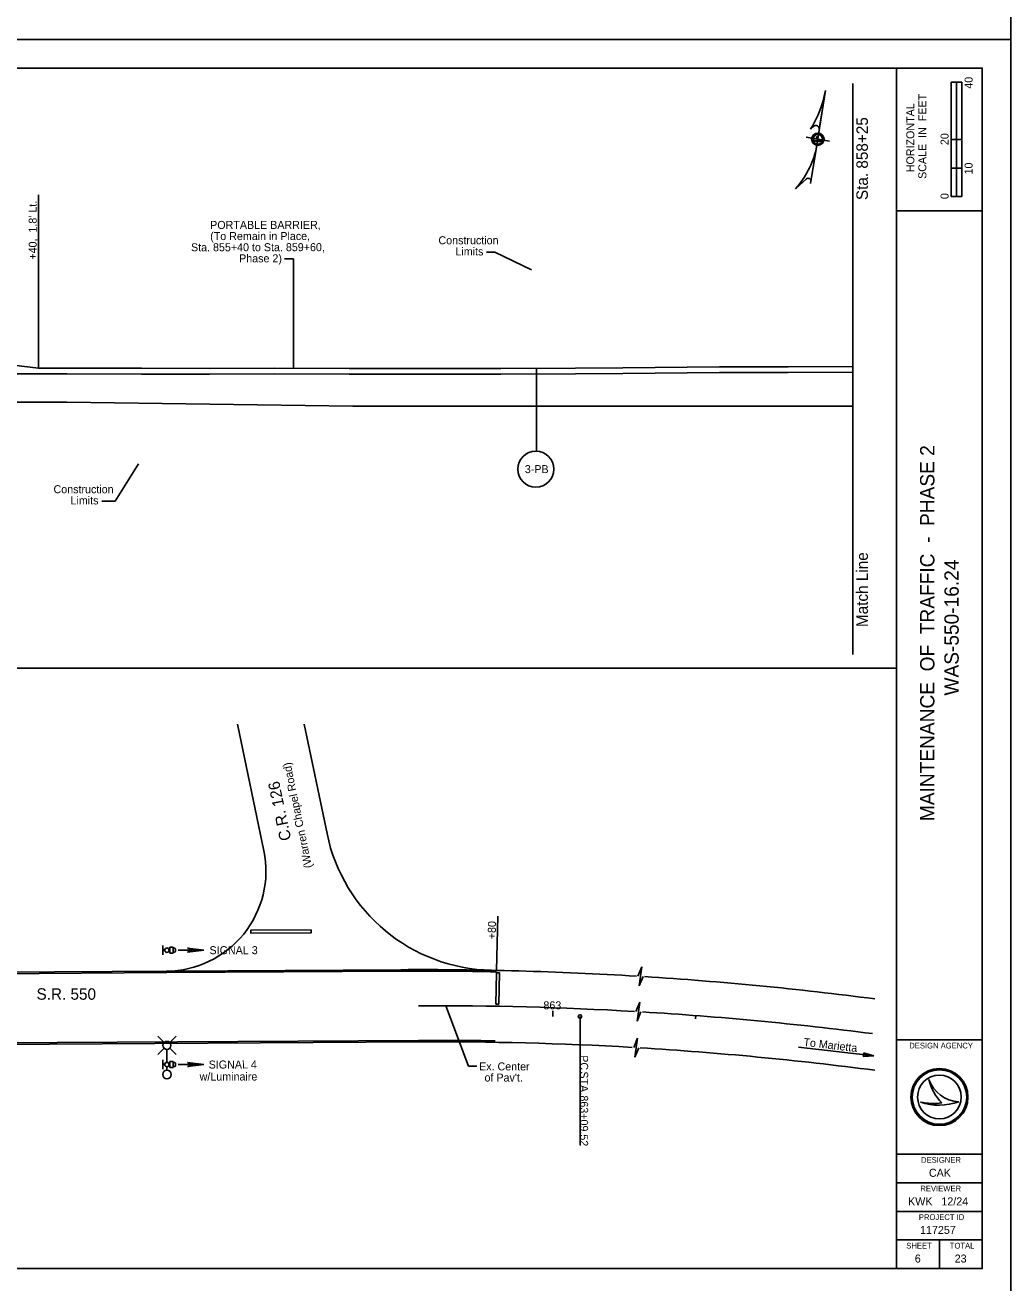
# Model space of a CAD drawing. Extents: x -1395 to 1843, y -1176 to 1887.
# Drawn here: x 335.1 to 680, y -435 to 5 of the extents above; entities that cross this region are included whole.
import ezdxf

# ---------------------------------------------------------------- set-up
doc = ezdxf.new("R2010")
doc.units = 0
for name, color, linetype in [('Default', 7, 'Continuous'), ('DR_P_Headwall', 7, 'Continuous'), ('DR_X_Ditch', 7, 'Continuous'), ('PV_X_COP', 7, 'Continuous'), ('SH_Border', 7, 'Continuous'), ('SH_Cut_Line', 7, 'Continuous'), ('SH_Major_Grid_Line', 7, 'Continuous'), ('SH_Masking', 7, 'Continuous'), ('SH_Named_Boundary', 7, 'Continuous'), ('SH_Text', 7, 'Continuous'), ('XS_P_Annotation', 7, 'Continuous'), ('XS_P_Headwall', 7, 'Continuous'), ('XS_P_Pavt_Surface', 7, 'Continuous')]:
    doc.layers.add(name, color=color, linetype=linetype)

msp = doc.modelspace()

# ---------------------------------------------------------------- linework, layer by layer
at = {"layer": 'Default'}
for p, q in [((628.34, -355.8), (632.08, -355.62)), ((628.34, -355.8), (628.34, -355.8)), ((632.08, -355.62), (628.47, -354.57)), ((628.47, -354.57), (628.47, -354.57))]:
    msp.add_line(p, q, dxfattribs=at)
for centre, radius, start, end in [((479.68, -1525.67), 1187.6, 86.68927, 90.33829), ((479.68, -1525.67), 1187.6, 82.65249, 86.55287), ((627.47, -355.08), 1.12, 320.4114, 27.0922)]:
    msp.add_arc(centre, radius, start, end, dxfattribs=at)
at = {"layer": 'DR_P_Headwall'}
for points in [[(435.21, -311.5), (435.21, -312.5), (414.02, -312.63), (414.01, -311.63)], [(500.8, -337.51), (499.8, -337.49), (500.03, -326.49), (501.03, -326.51)]]:
    msp.add_lwpolyline(points, close=True, dxfattribs=at)
at = {"layer": 'DR_X_Ditch'}
for p, q in [((409.39, -239.52), (418.6, -283.84)), ((432.77, -239.52), (440.71, -277.84)), ((233.82, -326.93), (466.57, -325.44)), ((233.34, -352.11), (472.74, -350.69))]:
    msp.add_line(p, q, dxfattribs=at)
for centre, radius, start, end in [((499.46, -265.66), 60, 191.7125, 268.8811), ((384.34, -290.97), 35, 270.365, 11.7448), ((474.37, -1550.42), 1225, 86.5054, 90.36504), ((474.37, -1550.42), 1225, 82.58979, 86.37543), ((479.68, -1525.67), 1175, 86.69128, 90.33829), ((479.68, -1525.67), 1175, 82.53374, 86.55625)]:
    msp.add_arc(centre, radius, start, end, dxfattribs=at)
at = {"layer": 'PV_X_COP'}
for p, q in [((189.71, -126.86), (349.71, -126.92)), ((349.71, -126.92), (449.71, -128.32)), ((449.71, -128.32), (624.71, -128.32)), ((169.71, -327.93), (384.56, -326.47)), ((384.71, -326.47), (466.57, -325.94)), ((233.33, -351.61), (472.74, -350.19))]:
    msp.add_line(p, q, dxfattribs=at)
msp.add_lwpolyline([(624.71, -116.41), (602.06, -116.52), (578.01, -116.55), (544.19, -116.91), (527.68, -117.01), (501.52, -117.12), (475.76, -117.1), (448.47, -117.14), (422.43, -116.96), (399.61, -117.13), (375.74, -117.06), (349.71, -117.04), (301.59, -117.04)], dxfattribs=at)
for centre, radius, start, end in [((474.37, -1550.42), 1224.5, 88.79875, 90.36504), ((479.68, -1525.67), 1175.5, 89.03216, 90.33829)]:
    msp.add_arc(centre, radius, start, end, dxfattribs=at)
at = {"layer": 'SH_Border'}
for points in [[(0, 0), (680, 0), (680, 440), (0, 440)], [(0, -440), (680, -440), (680, 0), (0, 0)]]:
    msp.add_lwpolyline(points, close=True, dxfattribs=at)
at = {"layer": 'SH_Cut_Line'}
for p, q in [((640, -430), (640, -10)), ((640, -60), (670, -60)), ((640, -350), (670, -350)), ((640, -390), (670, -390)), ((640, -400), (670, -400)), ((640, -410), (670, -410)), ((640, -420), (670, -420))]:
    msp.add_line(p, q, dxfattribs=at)
msp.add_lwpolyline([(30, -10), (670, -10), (670, -430), (30, -430)], close=True, dxfattribs=at)
at = {"layer": 'SH_Major_Grid_Line'}
msp.add_line((276.03, -220), (640, -220), dxfattribs=at)
msp.add_circle((513.76, -150.32), 6.29, dxfattribs=at)
at = {"layer": 'SH_Masking'}
msp.add_line((529.24, -341.82), (529.24, -386.82), dxfattribs=at)
msp.add_circle((529.24, -341.82), 0.6, dxfattribs=at)
at = {"layer": 'SH_Named_Boundary'}
for p, q in [((659.13, -55), (659.13, -15)), ((662.88, -15), (659.13, -15)), ((659.13, -35), (659.13, -15)), ((659.13, -15), (661, -15)), ((661, -15), (661.02, -15)), ((661.02, -15), (661.02, -35)), ((662.88, -15), (662.88, -55)), ((615.09, -17.9), (611.83, -38.41)), ((615.09, -17.9), (612.91, -31.42)), ((611, -30.4), (609.85, -31.41)), ((608.38, -34.21), (616.54, -35.57)), ((612.91, -31.42), (612.91, -31.42)), ((661.02, -35), (659.13, -35)), ((662.87, -35), (661, -35)), ((661, -35), (661, -45)), ((662.87, -45), (662.87, -35)), ((609.94, -50.35), (611.83, -38.41)), ((661, -45), (659.13, -45)), ((659.13, -45), (659.13, -55)), ((661, -55), (661, -45)), ((661, -45), (662.87, -45)), ((604.64, -52.24), (608.5, -48.81)), ((604.64, -52.23), (604.64, -52.24)), ((604.64, -52.24), (604.64, -52.24)), ((662.88, -55), (659.13, -55)), ((659.13, -55), (661, -55)), ((500.45, -306.71), (500.05, -325.69)), ((549.5, -327.75), (550.85, -324.5)), ((550.85, -324.5), (549.94, -331.06)), ((549.94, -331.06), (551.29, -327.82)), ((548.78, -340.1), (550.13, -336.85)), ((550.13, -336.85), (549.21, -343.42)), ((549.21, -343.42), (550.56, -340.17)), ((548.03, -352.68), (549.38, -349.43)), ((549.38, -349.43), (548.47, -356)), ((548.47, -356), (549.82, -352.75)), ((605.75, -352.51), (632.08, -355.62)), ((651.35, -363.81), (651.35, -363.81)), ((648.34, -371.81), (648.34, -371.81)), ((655, -370), (655, -370)), ((661.75, -371.63), (661.75, -371.63)), ((655, -430), (655, -420)), ((647.5, -426.5), (647.5, -426.5))]:
    msp.add_line(p, q, dxfattribs=at)
for centre, radius in [((612.46, -34.92), 2.17), ((612.46, -34.92), 1.7), ((655, -370), 10), ((655, -370), 9.54), ((655, -370), 9.54), ((655, -370), 7.64)]:
    msp.add_circle(centre, radius, dxfattribs=at)
for centre, radius, start, end in [((578.36, -11.42), 37.3, 327.6016, 350.0038), ((611.77, -31.27), 1.16, 352.6305, 131.7143), ((614.39, -33.05), 2.61, 200.2874, 259.2391), ((624.3, -29.81), 13.05, 198.5288, 205.362), ((581.22, -31.28), 31.43, 318.1774, 346.8959), ((612.05, -31.31), 4.12, 255.8713, 276.4809), ((612.95, -31.14), 4.58, 245.372, 281.9173), ((609.12, -49.51), 0.936, 350.9817, 131.6305), ((662.32, -360.05), 11.6, 198.9257, 198.9319), ((666.93, -360.6), 15.91, 191.6379, 191.6421), ((662.32, -360.05), 11.6, 198.9319, 267.1657), ((666.93, -360.6), 15.91, 191.6421, 226.0947), ((654.79, -352.6), 20.26, 251.4576, 290.0832), ((652.96, -346.91), 25.32, 259.4964, 259.4995), ((654.79, -352.6), 20.26, 251.4527, 251.4576), ((652.96, -346.91), 25.32, 259.4995, 276.6672)]:
    msp.add_arc(centre, radius, start, end, dxfattribs=at)
at = {"layer": 'SH_Text'}
for p, q in [((383.31, -320.27), (383.3, -316.98)), ((383.3, -318.52), (383.96, -318.52)), ((383.3, -318.72), (383.96, -318.72)), ((385.46, -318.52), (385.73, -318.52)), ((385.46, -318.72), (385.73, -318.72)), ((385.73, -319.63), (385.72, -317.61)), ((386.88, -317.61), (385.72, -317.61)), ((386.87, -319.62), (385.73, -319.63)), ((386.87, -319.62), (386.87, -317.61)), ((387.36, -317.91), (386.88, -317.91)), ((387.36, -319.35), (386.88, -319.35)), ((388.6, -318.56), (397.55, -318.56)), ((391.92, -317.86), (397.55, -318.56)), ((397.55, -318.56), (391.92, -319.26)), ((383.72, -350.92), (381.54, -348.74)), ((385.7, -350.92), (387.89, -348.74)), ((383.72, -352.9), (381.54, -355.08)), ((384.71, -357.86), (384.71, -353.31)), ((385.7, -352.9), (387.89, -355.08)), ((383.3, -360.26), (383.3, -356.97)), ((383.3, -358.52), (383.96, -358.52)), ((383.3, -358.72), (383.96, -358.72)), ((384.71, -360.63), (384.71, -359.38)), ((385.46, -358.52), (385.73, -358.52)), ((385.46, -358.72), (385.73, -358.72)), ((385.73, -359.63), (385.73, -357.61)), ((386.88, -357.61), (385.73, -357.61)), ((386.87, -359.63), (385.73, -359.63)), ((386.87, -359.63), (386.87, -357.61)), ((387.36, -357.92), (386.88, -357.92)), ((387.36, -359.36), (386.88, -359.36)), ((388.61, -358.62), (397.55, -358.62)), ((391.93, -357.92), (397.55, -358.62)), ((397.55, -358.62), (391.93, -359.32))]:
    msp.add_line(p, q, dxfattribs=at)
for centre, radius in [((384.71, -318.62), 0.757), ((384.71, -351.91), 1.4), ((384.71, -362.13), 1.5), ((384.71, -358.62), 0.757)]:
    msp.add_circle(centre, radius, dxfattribs=at)
for centre, radius in [((391.92, -318.56), 0.702), ((391.93, -358.62), 0.703)]:
    msp.add_arc(centre, radius, 270, 90, dxfattribs=at)
for centre, major_axis in [((387.36, -318.63), (0.001, -0.721)), ((387.36, -358.64), (0, -0.721))]:
    msp.add_ellipse(centre, major_axis=major_axis, ratio=0.45371, start_param=0, end_param=3.141593, dxfattribs=at)
at = {"layer": 'XS_P_Annotation'}
for p, q in [((519.71, -341.82), (519.71, -339.82)), ((569.7, -342.68), (569.75, -341.48))]:
    msp.add_line(p, q, dxfattribs=at)
at = {"layer": 'XS_P_Headwall'}
msp.add_line((339.71, -115.04), (304, -110.54), dxfattribs=at)
msp.add_lwpolyline([(339.71, -115.04), (349.71, -115.04), (375.74, -115.06), (399.61, -115.13), (422.43, -114.96), (448.47, -115.14), (475.76, -115.1), (501.52, -115.12), (527.67, -115.02), (544.18, -114.91), (578, -114.55), (602.06, -114.52), (624.7, -114.41)], dxfattribs=at)
at = {"layer": 'XS_P_Pavt_Surface'}
for p, q in [((624.71, -15.45), (624.71, -116.82)), ((339.71, -115.04), (339.71, -54.33)), ((496.56, -74.42), (499.4, -74.42)), ((512.21, -80.56), (499.4, -74.42)), ((428.97, -76.74), (425.82, -76.74)), ((428.97, -115.05), (428.97, -76.74)), ((513.98, -115.01), (513.98, -144.03)), ((624.71, -116.82), (624.71, -215.15)), ((374.71, -148.47), (366.59, -161.52)), ((361.87, -161.52), (366.59, -161.52)), ((490.17, -359.15), (482.27, -338.08)), ((490.17, -359.15), (493.19, -359.15))]:
    msp.add_line(p, q, dxfattribs=at)

# ---------------------------------------------------------------- texts
at = {"layer": 'DR_X_Ditch'}
for s, p in [('Sta. 858+25', (629.96, -56.2)), ('Match Line', (629.96, -205.57))]:
    msp.add_text(s, height=4, rotation=90, dxfattribs=at).set_placement(p)
at = {"layer": 'SH_Masking'}
for s, p in [('PC', (529.28, -355.39)), (' STA. ', (529.28, -359.98)), ('863+09.52', (529.28, -369.43))]:
    msp.add_text(s, height=2.8, rotation=270, dxfattribs=at).set_placement(p)
at = {"layer": 'SH_Named_Boundary'}
for s, height, rotation, p in [('40', 2.8, 90, (666.62, -17.23)), ('SCALE  IN  FEET', 2.8, 90, (650.42, -48.8)), ('HORIZONTAL', 2.8, 90, (646.22, -46.46)), ('20', 2.8, 90, (658.21, -36.96)), ('10', 2.8, 90, (666.62, -47.23)), ("+40,  1.8' Lt.", 2.8, 90.0561, (339.14, -77.04)), ('0', 2.8, 90, (658.21, -55.85)), ('PORTABLE BARRIER,', 2.8, 0.0561, (399.82, -66.3)), ('(To Remain in Place,', 2.8, 0.0561, (399.83, -70.2)), ('Construction', 2.8, 359.9439, (479.71, -71.65)), ('Sta. 855+40 to Sta. 859+60,', 2.8, 0.0561, (393.12, -74.11)), ('Limits', 2.8, 359.9439, (485.65, -75.55)), ('Phase 2)', 2.8, 0.0561, (409.95, -77.99)), ('MAINTENANCE  OF  TRAFFIC  -  PHASE 2', 5, 90, (653.25, -273.46)), ('3-PB', 2.8, 359.9439, (509.92, -151.72)), ('Construction', 2.8, 359.9439, (345.01, -158.75)), ('Limits', 2.8, 359.9439, (350.96, -162.66)), ('WAS-550-16.24', 5, 90, (661.75, -229.54)), ('+80', 2.8, 88.8548, (499.72, -314.81)), ('SIGNAL 3', 2.8, 0.0561, (399.6, -320.03)), ('S.R. 550', 4, 359.9439, (339.06, -335.94)), ('To Marietta', 2.8, 353.3262, (607.3, -352.08)), ('SIGNAL 4', 2.8, 0.0871, (399.3, -360.03)), ('Ex. Center', 2.8, 359.9439, (493.92, -360.67)), ('w/Luminaire', 2.8, 0.0871, (396.14, -364.24)), ("of Pav't.", 2.8, 359.9439, (495.83, -364.57))]:
    msp.add_text(s, height=height, rotation=rotation, dxfattribs=at).set_placement(p)
for s, height, p in [('DESIGN AGENCY', 2, (644.45, -353)), ('DESIGNER', 2, (648.57, -393)), ('CAK', 2.8, (651.33, -397.9)), ('REVIEWER', 2, (648.33, -403)), ('KWK   12/24', 2.8, (644.04, -407.9)), ('PROJECT ID', 2, (647.8, -413)), ('117257', 2.8, (648.23, -417.9)), ('SHEET', 2, (643.39, -423)), ('TOTAL', 2, (658.63, -423)), ('6', 2.8, (646.38, -427.9)), ('23', 2.8, (660.35, -427.9))]:
    msp.add_text(s, height=height, dxfattribs=at).set_placement(p)
at = {"layer": 'XS_P_Annotation'}
msp.add_text('863', height=2.8, rotation=0, dxfattribs=at).set_placement((516.44, -339.32))
at = {"layer": 'XS_P_Headwall'}
for s, height, p in [('(Warren Chapel Road)', 2.8, (435.54, -289.62)), ('C.R. 126', 4, (428.22, -279.91))]:
    msp.add_text(s, height=height, rotation=101.7125, dxfattribs=at).set_placement(p)

doc.saveas('drawing.dxf')
